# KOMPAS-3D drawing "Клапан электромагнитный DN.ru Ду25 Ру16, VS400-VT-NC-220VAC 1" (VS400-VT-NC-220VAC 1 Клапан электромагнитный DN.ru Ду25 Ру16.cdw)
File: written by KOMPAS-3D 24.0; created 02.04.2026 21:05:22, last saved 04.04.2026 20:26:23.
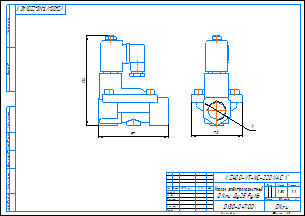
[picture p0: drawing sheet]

Document properties: c3d_UniqueCompID: ef56311e-7521-43dc-8291-0e6108b3d81d; Обозначение: VS400-ET-NC-220VAC 1; Наименование: Клапан электромагнитный DN.ru Ду25 Ру16; Автор: artio; Класс точности: c; Знак неуказанной шероховатости: Шероховатость не задана; Рассекать на разрезах: Да; c3d_UniqueCompID: ef56311e-7521-43dc-8291-0e6108b3d81d; Обозначение: VS400-ET-NC-220VAC 1-2; Наименование: Клапан электромагнитный DN.ru Ду15 Ру16; Автор: artio; Класс точности: c; Знак неуказанной шероховатости: Шероховатость не задана; Рассекать на разрезах: Да; c3d_UniqueCompID: ef56311e-7521-43dc-8291-0e6108b3d81d; Обозначение: VS400-ET-NC-220VAC 3-4; Наименование: Клапан электромагнитный DN.ru Ду20 Ру16; Автор: artio; Класс точности: c; Знак неуказанной шероховатости: Шероховатость не задана; Рассекать на разрезах: Да; c3d_UniqueCompID: ef56311e-7521-43dc-8291-0e6108b3d81d; Обозначение: VS400-ET-NC-220VAC 3-8; Наименование: Клапан электромагнитный DN.ru Ду10 Ру16; Автор: artio; Класс точности: c; Знак неуказанной шероховатости: Шероховатость не задана; Рассекать на разрезах: Да; Автор: artio; Форматы листов документа: A3; Полное имя файла: VS400-VT-NC-220VAC 1 Клапан электромагнитный DN.ru Ду25 Ру16.m3d; Масса: 1.524; Наименование: Клапан электромагнитный DN.ru Ду25 Ру16; Количество листов документа: 1; Примечание: D130-04700

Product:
- Body: Тело 1  | qty 1
    Масса: 1.76797
- Part/product: Клапан электромагнитный DN.ru Ду25 Ру16  | designation VS400-VT-NC-220VAC 1
    Масса: 1.524
    Раздел спецификации: Прочие изделия
    Примечание: D130-04700
    additional columns: ef56311e-7521-43dc-8291-0e6108b3d81d; VS400-ET-NC-220VAC 1; artio; c; Шероховатость не задана; Да

Views: Вид 1, Спереди, Проекционный вид 2
Referenced files in C:\Users\artio\OneDrive\Рабочий стол\Клапан электромагнитный DN.ru VS4x-xT-NC-x\DN10\: VS400-ET-NC-220VAC 3-8 Клапан электромагнитный DN.ru Ду10 Ру16.m3d, VS400-ET-NC-220VAC 3-8 Клапан электромагнитный DN.ru Ду10 Ру16.cdw
Referenced files in C:\Users\artio\OneDrive\Рабочий стол\Клапан электромагнитный DN.ru\VS400-VT-NC\VS400-VT-NC-220VAC\: VS400-VT-NC-220VAC 1 Клапан электромагнитный DN.ru Ду25 Ру16.m3d
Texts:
  VS400-VT-NC-220VAC 1
  Линейный размер
  Клапан электромагнитный
  DN.ru Ду25 Ру16
  VS400-VT-NC-220VAC 1"
  VS400-VT-NC-220VAC 1"-
  Клапан электромагнитный DN.ru Ду25 Ру16
  VS400-VT-NC-220VAC 1 Клапан электромагнитный DN.ru Ду25 Ру16
Dimensions and other numbers on the sheet: 0; 3; 2; 4; 70; 97; 124; 1:1; 1; 1,52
